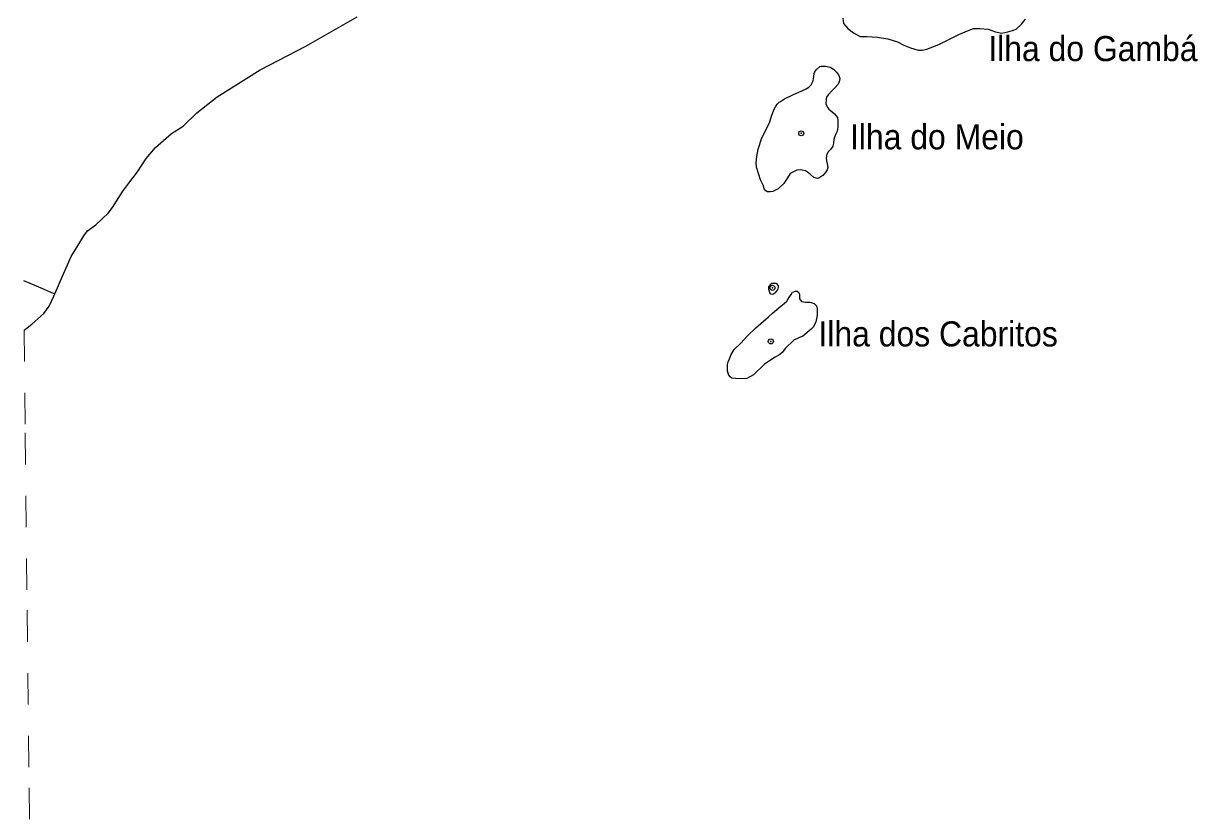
# Model space of a CAD drawing. Extents: x 317.8 to 344.1, y 7676.8 to 7704.8.
# Drawn here: x 317.918 to 321.659, y 7691.434 to 7693.947 of the extents above; entities that cross this region are included whole.
import ezdxf

# ---------------------------------------------------------------- set-up
doc = ezdxf.new("R2010")
doc.units = 0
doc.header["$LTSCALE"] = 0.032
doc.header["$PDMODE"] = 32
doc.header["$PDSIZE"] = 0.016
doc.linetypes.add('SHORT_DASHED', pattern=[2.7, 1.5, -1.2])
for name, color, linetype, lineweight in [('2', 7, 'Continuous', 25), ('62', 7, 'SHORT_DASHED', 13), ('7', 7, 'Continuous', 25)]:
    doc.layers.add(name, color=color, linetype=linetype, lineweight=lineweight)
doc.layers.add('54', color=7, linetype='Continuous')

msp = doc.modelspace()

# ---------------------------------------------------------------- linework, layer by layer
at = {"layer": '2'}
for points in [[(318.0178, 7693.0858), (318.0263, 7693.1052), (318.035, 7693.1251), (318.07, 7693.2052), (318.0918, 7693.2416), (318.1108, 7693.2708), (318.1224, 7693.2868), (318.1487, 7693.3058), (318.188, 7693.3436), (318.2011, 7693.3611), (318.2346, 7693.4136), (318.2536, 7693.4385), (318.2813, 7693.4748), (318.3089, 7693.517), (318.3381, 7693.552), (318.3891, 7693.5972), (318.427, 7693.6205), (318.4707, 7693.6627), (318.5348, 7693.7137), (318.6718, 7693.7997), (318.8175, 7693.8755), (318.9807, 7693.9687)], [(320.5281, 7693.9643), (320.531, 7693.9469), (320.5441, 7693.9308), (320.563, 7693.9177), (320.5834, 7693.9061), (320.6053, 7693.9061), (320.6388, 7693.9032), (320.6723, 7693.8988), (320.7029, 7693.8886), (320.7233, 7693.8784), (320.7437, 7693.8696), (320.7685, 7693.8624), (320.7816, 7693.8624), (320.7962, 7693.8653), (320.834, 7693.8798), (320.8981, 7693.9119), (320.9258, 7693.9235), (320.9448, 7693.9308), (320.9652, 7693.9308), (320.9914, 7693.9294), (321.0147, 7693.9206), (321.0351, 7693.9163), (321.0541, 7693.9206), (321.0686, 7693.925), (321.0803, 7693.9294), (321.0978, 7693.9454), (321.1109, 7693.9614)], [(317.9197, 7692.971), (317.9447, 7692.9896), (317.9826, 7693.0231), (318, 7693.0464), (318.0146, 7693.0785), (318.0178, 7693.0858)]]:
    msp.add_lwpolyline(points, dxfattribs=at)
for points in [[(320.2705, 7693.5835), (320.2951, 7693.6308), (320.3023, 7693.6555), (320.3075, 7693.6689), (320.3095, 7693.674), (320.3137, 7693.6822), (320.3188, 7693.6905), (320.326, 7693.6966), (320.3301, 7693.6987), (320.3425, 7693.7069), (320.3713, 7693.7213), (320.3959, 7693.7316), (320.4114, 7693.7388), (320.4206, 7693.7439), (320.4289, 7693.7532), (320.4289, 7693.7542), (320.434, 7693.7645), (320.4361, 7693.7769), (320.4371, 7693.7892), (320.4412, 7693.7964), (320.4433, 7693.7995), (320.4556, 7693.8098), (320.4597, 7693.8118), (320.4659, 7693.8118), (320.4731, 7693.8118), (320.4885, 7693.8077), (320.4988, 7693.8016), (320.5081, 7693.7923), (320.5142, 7693.7841), (320.5173, 7693.7779), (320.5194, 7693.7717), (320.5163, 7693.7614), (320.5132, 7693.7542), (320.5029, 7693.7419), (320.4947, 7693.7337), (320.4813, 7693.7203), (320.4762, 7693.7121), (320.4751, 7693.7069), (320.4741, 7693.6905), (320.4803, 7693.6791), (320.4844, 7693.674), (320.4937, 7693.6668), (320.5019, 7693.6596), (320.5111, 7693.6483), (320.5122, 7693.639), (320.5122, 7693.6339), (320.5122, 7693.6174), (320.5101, 7693.6041), (320.5081, 7693.5999), (320.5039, 7693.5907), (320.5019, 7693.5855), (320.4998, 7693.5773), (320.4988, 7693.567), (320.4978, 7693.5609), (320.4967, 7693.5567), (320.4906, 7693.5465), (320.4823, 7693.5382), (320.4772, 7693.531), (320.4751, 7693.5197), (320.4762, 7693.5094), (320.4782, 7693.5002), (320.4803, 7693.4889), (320.4782, 7693.4806), (320.4721, 7693.4714), (320.4649, 7693.4631), (320.4525, 7693.4549), (320.4474, 7693.4539), (320.4361, 7693.457), (320.4258, 7693.4662), (320.4155, 7693.4734), (320.4093, 7693.4775), (320.3939, 7693.4806), (320.3815, 7693.4796), (320.3733, 7693.4755), (320.361, 7693.4693), (320.3527, 7693.4559), (320.3404, 7693.4374), (320.3229, 7693.421), (320.3054, 7693.4117), (320.2982, 7693.4107), (320.289, 7693.4107), (320.2828, 7693.4138), (320.2777, 7693.421), (320.2756, 7693.4302), (320.2663, 7693.4498), (320.2612, 7693.4662), (320.253, 7693.4899), (320.2519, 7693.5033), (320.254, 7693.5238), (320.2591, 7693.5465)], [(320.2914, 7693.1013), (320.2964, 7693.0887), (320.2989, 7693.0862), (320.3056, 7693.0853), (320.3149, 7693.0912), (320.3199, 7693.0979), (320.3224, 7693.1029), (320.3232, 7693.1071), (320.3232, 7693.1122), (320.3207, 7693.1155), (320.3165, 7693.1189), (320.3124, 7693.1189), (320.3056, 7693.1189), (320.3015, 7693.1189), (320.2981, 7693.1163), (320.2914, 7693.108)], [(320.2512, 7692.9781), (320.2922, 7693.0133), (320.304, 7693.025), (320.3308, 7693.0468), (320.3417, 7693.0552), (320.3501, 7693.0627), (320.3543, 7693.0702), (320.3635, 7693.0845), (320.3685, 7693.0912), (320.3727, 7693.0929), (320.3777, 7693.0946), (320.3828, 7693.0946), (320.3869, 7693.092), (320.3903, 7693.0853), (320.3903, 7693.0778), (320.3903, 7693.0702), (320.397, 7693.0619), (320.4096, 7693.0594), (320.423, 7693.0594), (320.428, 7693.0585), (320.4372, 7693.0552), (320.4448, 7693.0476), (320.4464, 7693.0384), (320.4464, 7693.0174), (320.4423, 7692.9965), (320.4355, 7692.9814), (320.428, 7692.9739), (320.4012, 7692.9512), (320.3878, 7692.9462), (320.3727, 7692.9387), (320.3459, 7692.9135), (320.335, 7692.8993), (320.3283, 7692.8934), (320.3124, 7692.8842), (320.2788, 7692.8624), (320.2436, 7692.828), (320.2227, 7692.8163), (320.2059, 7692.8155), (320.1866, 7692.8163), (320.1749, 7692.818), (320.1699, 7692.8222), (320.1657, 7692.8272), (320.1615, 7692.8398), (320.1615, 7692.8473), (320.1615, 7692.8616), (320.1632, 7692.8699), (320.1674, 7692.8792), (320.1732, 7692.8926), (320.1825, 7692.9085), (320.2034, 7692.9295), (320.2252, 7692.9521)]]:
    msp.add_lwpolyline(points, close=True, dxfattribs=at)
at = {"layer": '54'}
for p in [(320.3958, 7693.5974), (320.3042, 7693.1053), (320.2991, 7692.9346)]:
    msp.add_point(p, dxfattribs=at)
at = {"layer": '62'}
msp.add_lwpolyline([(317.9197, 7692.971), (317.9233, 7692.6431), (317.9294, 7692.0782), (317.9356, 7691.5134), (317.9417, 7690.9485)], dxfattribs=at)
at = {"layer": '7'}
msp.add_line((318.0178, 7693.0858), (318.0179, 7693.0858), dxfattribs=at)
msp.add_lwpolyline([(317.918, 7693.129), (317.9781, 7693.1029), (317.9927, 7693.0966), (318.0178, 7693.0858)], dxfattribs=at)

# ---------------------------------------------------------------- texts
at = {"layer": '54', "width": 0.95}
for s, p in [('Ilha do Gambá', (320.9919, 7693.8273)), ('Ilha do Meio', (320.5513, 7693.5463)), ('Ilha dos Cabritos', (320.4508, 7692.9187))]:
    msp.add_text(s, height=0.08, dxfattribs=at).set_placement(p)

doc.saveas('drawing.dxf')
